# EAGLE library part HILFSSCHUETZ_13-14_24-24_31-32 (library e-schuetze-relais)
Hilfsschütz mit 2 Schließern, 1 Öffner
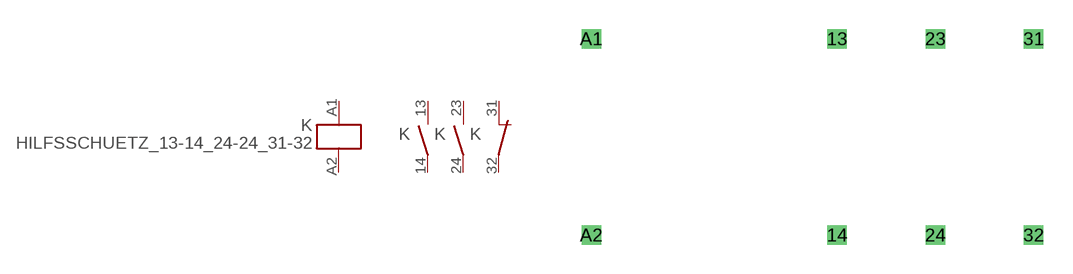
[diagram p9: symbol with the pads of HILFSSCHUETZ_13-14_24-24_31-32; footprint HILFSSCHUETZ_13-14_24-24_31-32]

Designator prefix K; gates G$1=SPULE 1=SCHLIESSER 2=SCHLIESSER 3=OEFFNER

## HILFSSCHUETZ_13-14_24-24_31-32  [HILFSSCHUETZ_13-14_24-24_31-32]
13  1:3  pas
14  1:4  pas
23  2:3  pas
24  2:4  pas
31  3:1  pas
32  3:2  pas
A1  G$1:A1  in
A2  G$1:A2  in

## Footprint HILFSSCHUETZ_13-14_24-24_31-32 (pad centres in mm)
Dummy
drill 0.5 pad 1 square: 13 2.54,5.08; 14 2.54,-5.08; 23 7.62,5.08; 24 7.62,-5.08; 31 12.7,5.08; 32 12.7,-5.08; A1 -10.16,5.08; A2 -10.16,-5.08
